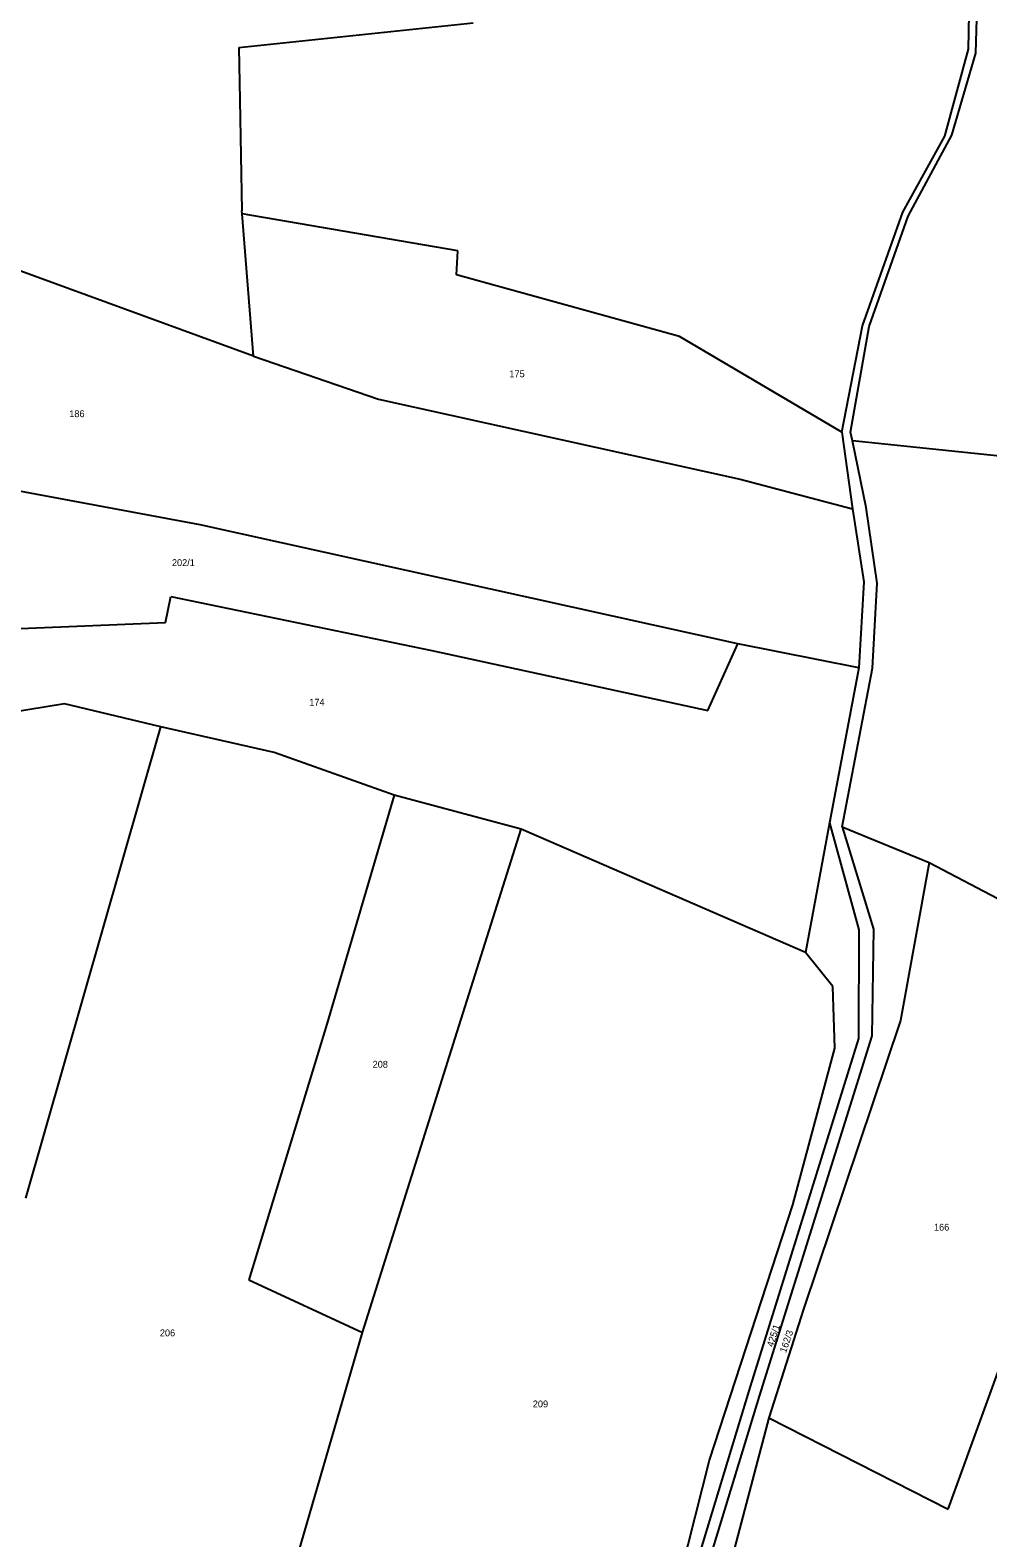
# Model space of a CAD drawing. Extents: x -791548 to -789311, y -1142631 to -1140855.
# Drawn here: x -790377.8 to -790140.3, y -1141623.3 to -1141249.5 of the extents above; entities that cross this region are included whole.
import ezdxf
from ezdxf.enums import TextEntityAlignment as Align

# ---------------------------------------------------------------- set-up
doc = ezdxf.new("R2010")
doc.units = 0
doc.header["$LTSCALE"] = 0.68
doc.layers.add('1', color=7, linetype='Continuous', lineweight=25)
doc.layers.add('2', color=7, linetype='Continuous')

msp = doc.modelspace()

# ---------------------------------------------------------------- linework, layer by layer
at = {"layer": '1'}
for p, q in [((-790145.1, -1141254.19), (-790144.31, -1141209.88)), ((-790143.29, -1141255.16), (-790142.1, -1141209.79)), ((-790326.03, -1141253.78), (-790267.94, -1141247.66)), ((-790326.03, -1141253.78), (-790325.79, -1141266.86)), ((-790151.04, -1141275.76), (-790145.1, -1141254.19)), ((-790149.25, -1141275.53), (-790143.29, -1141255.16)), ((-790325.79, -1141266.86), (-790325.29, -1141294.22)), ((-790161.43, -1141294.56), (-790151.04, -1141275.76)), ((-790160.11, -1141295.6), (-790149.25, -1141275.53)), ((-790325.23, -1141295.03), (-790325.29, -1141294.22)), ((-790322.4, -1141330.26), (-790325.23, -1141295.03)), ((-790271.77, -1141304.14), (-790325.23, -1141295.03)), ((-790171.41, -1141322.79), (-790161.43, -1141294.56)), ((-790169.74, -1141322.94), (-790160.11, -1141295.6)), ((-790322.4, -1141330.26), (-790407.51, -1141299.23)), ((-790272.04, -1141310.13), (-790271.77, -1141304.14)), ((-790216.75, -1141325.38), (-790272.04, -1141310.13)), ((-790176.53, -1141349.17), (-790171.41, -1141322.79)), ((-790174.39, -1141349.15), (-790169.74, -1141322.94)), ((-790176.53, -1141349.17), (-790216.75, -1141325.38)), ((-790322.4, -1141330.26), (-790291.39, -1141340.95)), ((-790291.39, -1141340.95), (-790201.73, -1141360.75)), ((-790176.53, -1141349.17), (-790173.92, -1141368.17)), ((-790173.91, -1141351.31), (-790174.39, -1141349.15)), ((-790170.48, -1141367.77), (-790173.91, -1141351.31)), ((-790124.52, -1141356.45), (-790173.91, -1141351.31)), ((-790335.65, -1141372.07), (-790399.6, -1141360.25)), ((-790201.73, -1141360.75), (-790173.92, -1141368.17)), ((-790173.92, -1141368.17), (-790171.09, -1141386.2)), ((-790167.81, -1141386.55), (-790170.48, -1141367.77)), ((-790202.36, -1141401.58), (-790335.65, -1141372.07)), ((-790171.09, -1141386.2), (-790172.35, -1141407.57)), ((-790168.95, -1141407.67), (-790167.81, -1141386.55)), ((-790344.25, -1141396.36), (-790342.86, -1141389.9)), ((-790342.86, -1141389.9), (-790278.16, -1141403.27)), ((-790434.62, -1141399.94), (-790344.25, -1141396.36)), ((-790209.79, -1141418.13), (-790202.36, -1141401.58)), ((-790172.35, -1141407.57), (-790202.36, -1141401.58)), ((-790278.16, -1141403.27), (-790209.79, -1141418.13)), ((-790172.35, -1141407.57), (-790179.63, -1141446)), ((-790176.45, -1141446.97), (-790168.95, -1141407.67)), ((-790369.23, -1141416.5), (-790382.93, -1141418.73)), ((-790345.36, -1141422.16), (-790369.23, -1141416.5)), ((-790378.88, -1141539.02), (-790345.36, -1141422.16)), ((-790317.27, -1141428.59), (-790345.36, -1141422.16)), ((-790287.5, -1141439.1), (-790317.27, -1141428.59)), ((-790287.5, -1141439.1), (-790304.23, -1141495.93)), ((-790256.02, -1141447.58), (-790287.5, -1141439.1)), ((-790179.63, -1141446), (-790185.56, -1141478.12)), ((-790179.63, -1141446), (-790172.3, -1141472.5)), ((-790176.45, -1141446.97), (-790168.66, -1141472.35)), ((-790176.45, -1141446.97), (-790154.9, -1141455.81)), ((-790271.91, -1141497.79), (-790256.02, -1141447.58)), ((-790185.56, -1141478.12), (-790256.02, -1141447.58)), ((-790154.9, -1141455.81), (-790162.02, -1141495.03)), ((-790154.9, -1141455.81), (-790132.85, -1141467.37)), ((-790172.3, -1141472.5), (-790172.43, -1141499.45)), ((-790168.66, -1141472.35), (-790169.13, -1141498.76)), ((-790178.75, -1141486.57), (-790185.56, -1141478.12)), ((-790178.24, -1141501.86), (-790178.75, -1141486.57)), ((-790162.02, -1141495.03), (-790186.05, -1141566.59)), ((-790304.23, -1141495.93), (-790323.53, -1141559.32)), ((-790295.42, -1141572.35), (-790271.91, -1141497.79)), ((-790172.43, -1141499.45), (-790199.57, -1141586.79)), ((-790169.13, -1141498.76), (-790197.01, -1141588.1)), ((-790188.65, -1141540.67), (-790178.24, -1141501.86)), ((-790209.39, -1141603.99), (-790188.65, -1141540.67)), ((-790323.53, -1141559.32), (-790295.42, -1141572.35)), ((-790186.05, -1141566.59), (-790194.67, -1141593.52)), ((-790150.16, -1141616.16), (-790131.39, -1141564.28)), ((-790332.51, -1141700.08), (-790295.42, -1141572.35)), ((-790199.57, -1141586.79), (-790220.35, -1141655.18)), ((-790197.01, -1141588.1), (-790217.52, -1141655.12)), ((-790194.67, -1141593.52), (-790208.68, -1141646.83)), ((-790194.67, -1141593.52), (-790150.16, -1141616.16)), ((-790227.63, -1141676.68), (-790209.39, -1141603.99))]:
    msp.add_line(p, q, dxfattribs=at)

# ---------------------------------------------------------------- texts
at = {"layer": '2'}
for s, p in [('175', (-790257.069, -1141335.522)), ('186', (-790366.189, -1141345.412)), ('202/1', (-790339.78, -1141382.322)), ('174', (-790306.679, -1141416.932)), ('208', (-790290.979, -1141506.702)), ('166', (-790151.799, -1141547.092)), ('206', (-790343.729, -1141573.292)), ('209', (-790251.259, -1141590.912))]:
    msp.add_text(s, height=1.7, dxfattribs=at).set_placement(p, align=Align.CENTER)
for s, rotation, p in [('425/1', 72, (-790192.716, -1141573.3617)), ('162/3', 71, (-790189.4682, -1141574.8167))]:
    msp.add_text(s, height=1.7, rotation=rotation, dxfattribs=at).set_placement(p, align=Align.CENTER)

doc.saveas('drawing.dxf')
